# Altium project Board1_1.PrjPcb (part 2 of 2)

## Sheet ETH,HDMI.schdoc
size 420 x 297 mm; Device: Drawing-Symbol_A4; @Board Name: Board1_1; @Page Name: ETH,HDMI; @Create Time: 13:52:28; @Page Count: 7; @Page No: 6; @Schematic Name: Schematic1_1; @Update Time: 13:52:28; @Assembly Variant: Basic; Border: 1; Title Block Position: 3; Size: A4; Region Start: 1; X Region Count: 6; Y Region Count: 4; Blade Width: 10; Width: 1655; Height: 1170; Symbol: Drawing-Symbol_A4; Company: 嘉立创EDA; Version: V1.0; Page Size: A4; @Project Name: N01｜全志 H6 Linux 主板; @Update Date: 2026-11-21; @Create Date: 2026-11-21
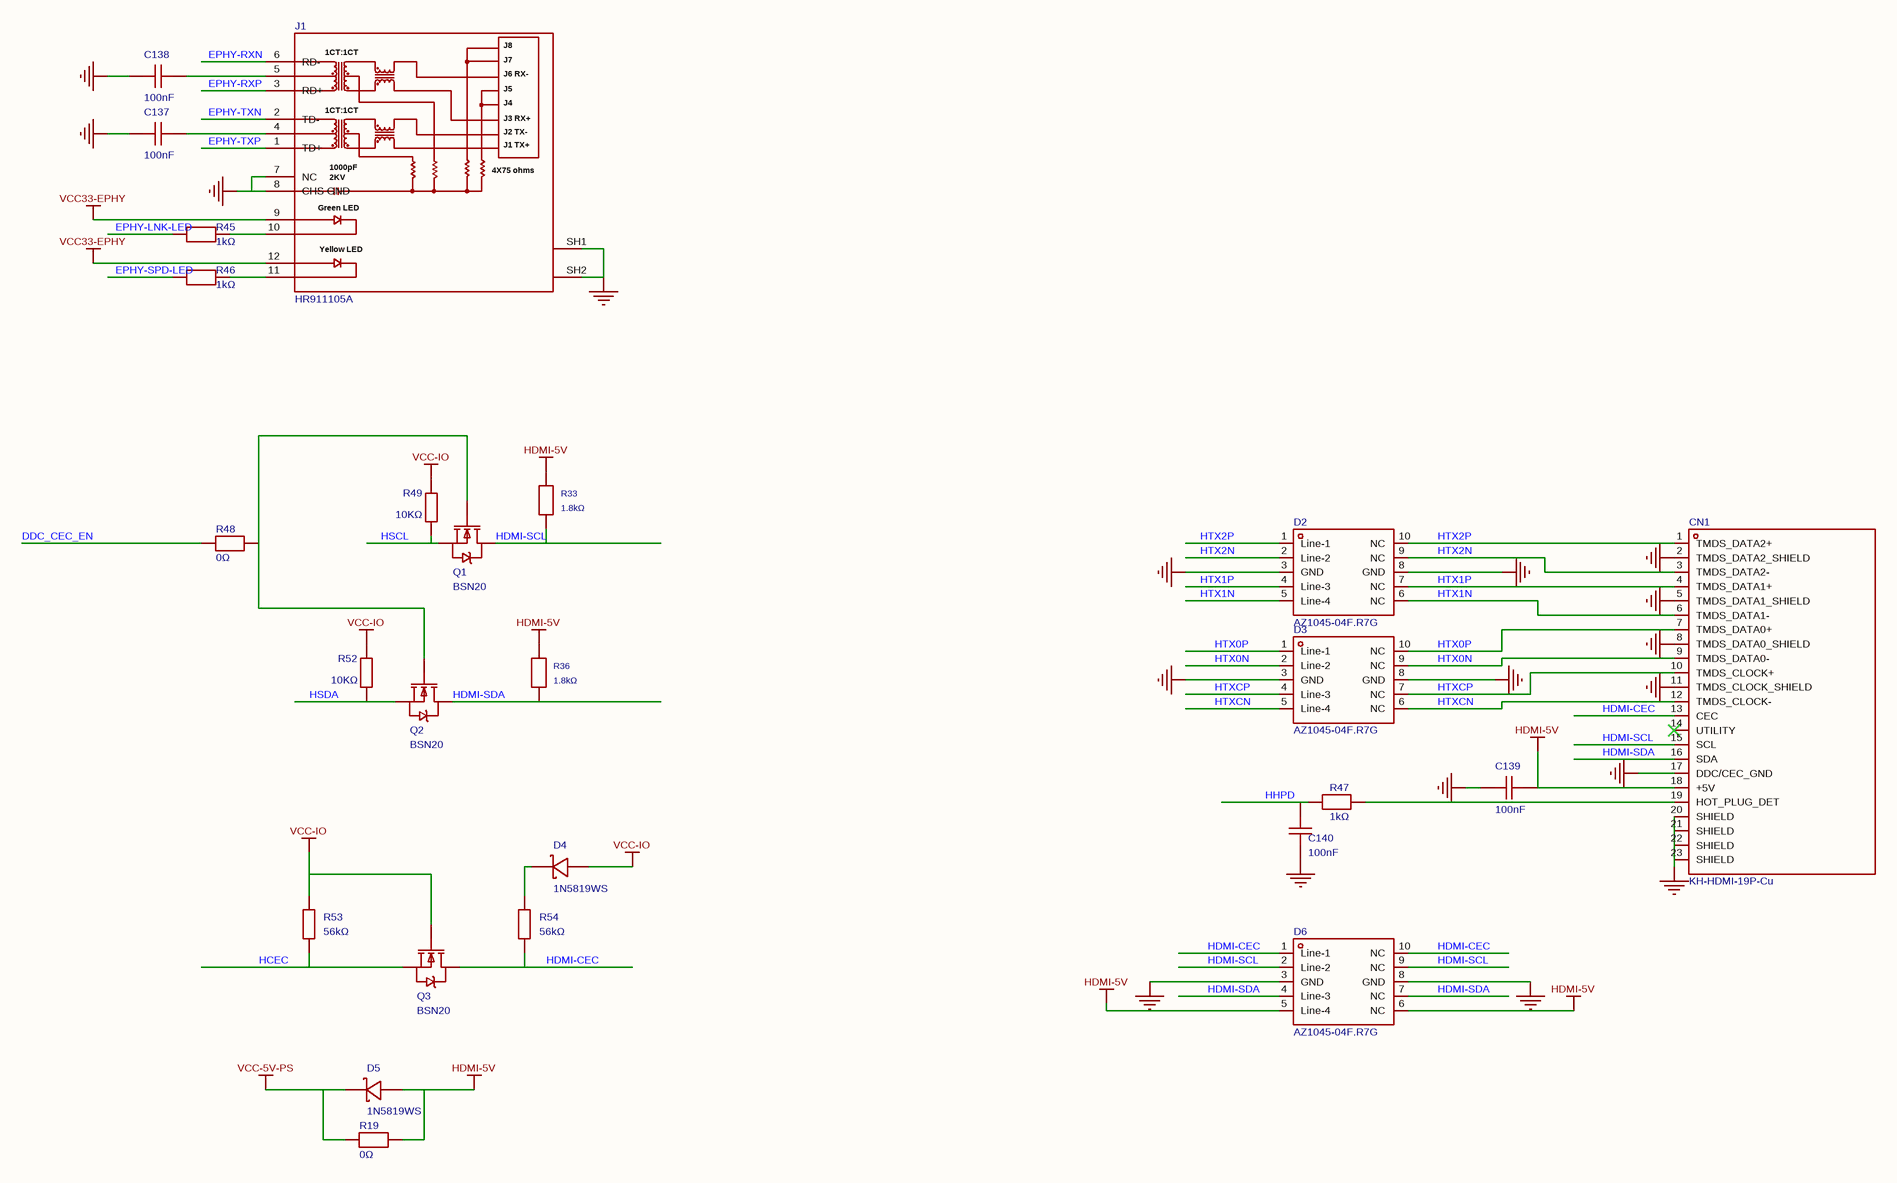
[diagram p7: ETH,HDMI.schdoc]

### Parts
C137  100nF  [C0603]
C138  100nF  [C0603]
C139  100nF  [C0402]
C140  100nF  [C0402]
CN1  KH-HDMI-19P-Cu  [HDMI-SMD_KH-HDMI-19P-CU]
D2  AZ1045-04F.R7G  [DFN2510-10_L2.5-W1.0-P0.50-BL]
D3  AZ1045-04F.R7G  [DFN2510-10_L2.5-W1.0-P0.50-BL]
D4  1N5819WS  [SOD-323_L1.8-W1.3-LS2.5-RD]
D5  1N5819WS  [SOD-323_L1.8-W1.3-LS2.5-RD]
D6  AZ1045-04F.R7G  [DFN2510-10_L2.5-W1.0-P0.50-BL]
J1  HR911105A  [RJ45-TH_HR911105A]
Q1  BSN20  [SOT-23-3_L2.9-W1.6-P1.90-LS2.8-BR]
Q2  BSN20  [SOT-23-3_L2.9-W1.6-P1.90-LS2.8-BR]
Q3  BSN20  [SOT-23-3_L2.9-W1.6-P1.90-LS2.8-BR]
R19  0Ω  [R0805]
R33  1.8kΩ  [R0805]
R36  1.8kΩ  [R0805]
R45  1kΩ  [R0805]
R46  1kΩ  [R0805]
R47  1kΩ  [R0805]
R48  0Ω  [R0805]
R49  10KΩ  [R0805]
R52  10KΩ  [R0805]
R53  56kΩ  [R0805]
R54  56kΩ  [R0805]

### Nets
GND: C137.1 C138.1 C139.2 C140.2 CN1.2(TMDS_DATA2_SHIELD) CN1.5(TMDS_DATA1_SHIELD) CN1.8(TMDS_DATA0_SHIELD) CN1.11(TMDS_CLOCK_SHIELD) CN1.17(DDC/CEC_GND) CN1.20(SHIELD) CN1.21(SHIELD) CN1.22(SHIELD) CN1.23(SHIELD) D2.3(GND) D2.8(GND) D3.3(GND) D3.8(GND) D6.3(GND) D6.8(GND) J1.7(NC) J1.8(CHS_GND) J1.SH1 J1.SH2
HDMI-5V: C139.1 CN1.18(+5V) D5.2(A) D6.5(Line-4) D6.6(NC) R19.2 R33.2 R36.2
VCC33-EPHY: J1.9 J1.12  [project net ALDO2]
VCC-5V-PS: D5.1(K) R19.1  [project net ALDOIN]
VCC-IO: D4.2(A) Q3.1(G) R49.1 R52.1 R53.2  [project net CLDO1]
DDC_CEC_EN: R48.1
EPHY-LNK-LED: R45.1
EPHY-RXN: J1.6(RD-)
EPHY-RXP: J1.3(RD+)
EPHY-SPD-LED: R46.1
EPHY-TXN: J1.2(TD-)
EPHY-TXP: J1.1(TD+)
HCEC: Q3.2(S) R53.1
HDMI-CEC: CN1.13(CEC) D6.1(Line-1) D6.10(NC) Q3.3(D) R54.1
HDMI-SCL: CN1.15(SCL) D6.2(Line-2) D6.9(NC) Q1.3(D) R33.1
HDMI-SDA: CN1.16(SDA) D6.4(Line-3) D6.7(NC) Q2.3(D) R36.1
HHPD: C140.1 R47.1
HSCL: Q1.2(S) R49.2
HSDA: Q2.2(S) R52.2
HTX0N: CN1.9(TMDS_DATA0-) D3.2(Line-2) D3.9(NC)
HTX0P: CN1.7(TMDS_DATA0+) D3.1(Line-1) D3.10(NC)
HTX1N: CN1.6(TMDS_DATA1-) D2.5(Line-4) D2.6(NC)
HTX1P: CN1.4(TMDS_DATA1+) D2.4(Line-3) D2.7(NC)
HTX2N: CN1.3(TMDS_DATA2-) D2.2(Line-2) D2.9(NC)
HTX2P: CN1.1(TMDS_DATA2+) D2.1(Line-1) D2.10(NC)
HTXCN: CN1.12(TMDS_CLOCK-) D3.5(Line-4) D3.6(NC)
HTXCP: CN1.10(TMDS_CLOCK+) D3.4(Line-3) D3.7(NC)
NetC137_2: C137.2 J1.4
NetC138_2: C138.2 J1.5
NetCN1_19: CN1.19(HOT_PLUG_DET) R47.2
NetD4_1: D4.1(K) R54.2
NetJ1_10: J1.10 R45.2
NetJ1_11: J1.11 R46.2
NetQ1_1: Q1.1(G) Q2.1(G) R48.2

Not connected (* = marked no-connect by the designer): CN1 14(UTILITY)*

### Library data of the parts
C137 C138 = CC0603KRX7R9BB104: 容值:100nF;精度:±10%;额定电压:50V;温度系数:X7R;; Manufacturer: YAGEO(国巨); 3D Model: ac125912035d415993ca9572d50418b1¦0819f05c4eef4c71ace90d822a990e87; 3D Model Transform: 62.992,31.496,0,0,0,0,0,0,0; Tolerance: ±10%; Voltage Rating: 50V; Temperature Coefficient: X7R; AddInBom: yes; ModelName: C0603_L1.6-W0.8-H0.8
C139 C140 = CL05B104KO5NNNC: 容值:100nF;精度:±10%;额定电压:16V;温度系数:X7R;; Manufacturer: SAMSUNG(三星); 3D Model: 36a51122f27c49738f86b3bfa98863e0¦0819f05c4eef4c71ace90d822a990e87; 3D Model Transform: 39.37,19.685,0,0,0,0,0,0,0; Tolerance: ±10%; Voltage Rating: 16V; Temperature Coefficient: X7R; AddInBom: yes; ModelName: C0402_L1.0-W0.5-H0.5
CN1 = KH-HDMI-19P-Cu: HDMI高清头母座 19PIN 四脚插端子SMT; Manufacturer: kinghelm(金航标); AddInBom: yes; ModelId: 60339402b69c481f9aa5c918248ca672¦0819f05c4eef4c71ace90d822a990e87; ModelTransform: 590.55,466.5345,0,0,0,0,0.001,-78.739,-66.929; Connector Type: HDMI-A; Gender: 母
D2 = AZ1045-04F.R7G: 反向截止电压(Vrwm):5V;钳位电压:12V;峰值脉冲电流(Ipp):3.5A@8/20us;峰值脉冲功率(Ppp):30W@8/20us;击穿电压:6V;; Manufacturer: AMAZING(晶焱); AddInBom: yes; ModelId: 55525fa8fc914f7c8ffcb10749ea5f73¦0819f05c4eef4c71ace90d822a990e87; ModelName: DFN-10_L2.5-W1.0-H0.5-P0.50; ModelTransform: 40.1574,98.425,0,90,0,0,0,0,0; Reverse Stand-Off Voltage (Vrwm): 5V; Clamping Voltage: 12V; Voltage - Breakdown: 6V; Reverse Leakage Current (Ir): 1.5uA; Number of Channels: 四路; level of protection: IEC 61000-4-5；IEC 61000-4-2; Type: ESD; Junction Capacitance: 0.5pF
D3 D6 = AZ1045-04F.R7G: 反向截止电压(Vrwm):5V;钳位电压:12V;峰值脉冲电流(Ipp):3.5A@8/20us;峰值脉冲功率(Ppp):30W@8/20us;击穿电压:6V;; Manufacturer: AMAZING(晶焱); 3D Model: 55525fa8fc914f7c8ffcb10749ea5f73¦0819f05c4eef4c71ace90d822a990e87; 3D Model Transform: 40.1574,98.425,0,90,0,0,0,0,0; Reverse Stand-Off Voltage (Vrwm): 5V; Clamping Voltage: 12V; Voltage - Breakdown: 6V; Reverse Leakage Current (Ir): 1.5uA; Number of Channels: 四路; level of protection: IEC 61000-4-5；IEC 61000-4-2; Type: ESD; Junction Capacitance: 0.5pF; AddInBom: yes; ModelName: DFN-10_L2.5-W1.0-H0.5-P0.50
D4 D5 = 1N5819WS_C191023: 正向压降(Vf):600mV@1A;直流反向耐压(Vr):40V;整流电流:1A;; Manufacturer: Hottech(合科泰); AddInBom: yes; ModelId: db63db13d9e342eb939127d413d6200b¦0819f05c4eef4c71ace90d822a990e87; ModelTransform: 104.3305,51.181,0,0,0,0,0,-0.004,0; Voltage - DC Reverse(Vr): 40V; Current - Rectified: 1A; Non-Repetitive Peak Forward Surge Current: 25A
J1 = HR911105A_C12074: 连接器类型:RJ45插座;安装方式:弯插;端口数量:1;LED:带LED;屏蔽:有屏蔽;等级:-;触头材质:磷青铜;触头镀层:金;工作温度:0℃~+70℃;; Manufacturer: HANRUN(汉仁); 3D Model: 269ece015cf14129b359f9a66aa2dc0d¦0819f05c4eef4c71ace90d822a990e87; 3D Model Transform: 624.711,850.392,0,0,0,0,0,-89.567,-129.921; Connector Type: RJ45插座; Number of Ports: 1; LED: 带LED; Shielding: 有屏蔽; PoE: 不带PoE; Supplementary Features: 带滤波; AddInBom: yes
Q1-Q3 = BSN20_C116157: 数量:1个N沟道;漏源电压(Vdss):50V;连续漏极电流(Id):100mA;导通电阻(RDS(on)):10Ω@2.75V,0.2A;耗散功率(Pd):-;阈值电压(Vgs(th)):1.5V@250uA;; Manufacturer: SHIKUES(时科); AddInBom: yes; ModelId: 89cb27a44ab2466697082bb9fd73a7d0¦0819f05c4eef4c71ace90d822a990e87; ModelName: SOT-23-3L_L2.9-W1.6-H1.1-LS2.8-P0.95; ModelTransform: 114.173,110.236,0,90,0,0,0,0,0; Number: 1个N沟道; Drain to Source Voltage: 50V; Current - Continuous Drain(Id): 100mA; Input Capacitance(Ciss): 40pF; Reverse Transfer Capacitance (Crss@Vds): 10pF; Type: N沟道; Output Capacitance(Coss): 15pF
R19 R48 = RE0805FAR000: 电阻类型:合金电阻;阻值:0Ω;精度:±1%;功率:500mW;温度系数:±50ppm/℃;安装方式:贴片;; Manufacturer: JIERR(捷而瑞); 3D Model: 37a81e68749a4138bd2dfa6897b24b85¦0819f05c4eef4c71ace90d822a990e87; 3D Model Transform: 78.74,51.181,0,0,0,0,0,-0.0005,0; Tolerance: ±1%; Power(Watts): 500mW; AddInBom: yes; ModelName: R0805_L2.0-W1.3-H0.6
R33 R36 = FRP0805F1801TS: 电阻类型:厚膜电阻;阻值:1.8kΩ;精度:±1%;功率:250mW;工作电压:150V;温度系数:±100ppm/℃;; Manufacturer: FOJAN(富捷); AddInBom: yes; ModelId: 37a81e68749a4138bd2dfa6897b24b85¦0819f05c4eef4c71ace90d822a990e87; ModelName: R0805_L2.0-W1.3-H0.6; ModelTransform: 78.74,51.181,0,0,0,0,0,-0.0005,0; Tolerance: ±1%; Power(Watts): 250mW; Voltage-Supply(Max): 150V
R45-R47 = FRC0805F1001TS: 电阻类型:厚膜电阻;阻值:1kΩ;精度:±1%;功率:125mW;工作电压:150V;温度系数:±100ppm/℃;; Manufacturer: FOJAN(富捷); AddInBom: yes; ModelId: 37a81e68749a4138bd2dfa6897b24b85¦0819f05c4eef4c71ace90d822a990e87; ModelName: R0805_L2.0-W1.3-H0.6; ModelTransform: 78.74,51.181,0,0,0,0,0,-0.0005,0; Tolerance: ±1%; Power(Watts): 125mW; Voltage-Supply(Max): 150V
R49 R52 = 0805W8F1002T5E_C17414: 电阻类型:厚膜电阻;阻值:10kΩ;精度:±1%;功率:125mW;工作电压:150V;温度系数:±100ppm/℃;; Manufacturer: UNI-ROYAL(厚声); Add into BOM: yes; 3D Model: 37a81e68749a4138bd2dfa6897b24b85; 3D Model Transform: 78.74,51.181,0,0,0,0,0,-0.0005,0; Tolerance: ±1%; Power(Watts): 125mW; Voltage-Supply(Max): 150V; ModelName: R0805_L2.0-W1.3-H0.6
R53 R54 = 0805W8F5602T5E: 电阻类型:厚膜电阻;阻值:56kΩ;精度:±1%;功率:125mW;工作电压:150V;温度系数:±100ppm/℃;; Manufacturer: UNI-ROYAL(厚声); AddInBom: yes; ModelId: 37a81e68749a4138bd2dfa6897b24b85¦0819f05c4eef4c71ace90d822a990e87; ModelName: R0805_L2.0-W1.3-H0.6; ModelTransform: 78.74,51.181,0,0,0,0,0,-0.0005,0; Tolerance: ±1%; Power(Watts): 125mW; Voltage-Supply(Max): 150V

## Sheet KEY,DEBUG,LED.schdoc
size 420 x 297 mm; Device: Drawing-Symbol_A4; @Board Name: Board1_1; @Page Name: KEY,DEBUG,LED; @Create Time: 13:52:28; @Page Count: 7; @Page No: 7; @Schematic Name: Schematic1_1; @Update Time: 13:52:28; @Assembly Variant: Basic; Border: 1; Title Block Position: 3; Size: A4; Region Start: 1; X Region Count: 6; Y Region Count: 4; Blade Width: 10; Width: 1655; Height: 1170; Symbol: Drawing-Symbol_A4; Company: 嘉立创EDA; Version: V1.0; Page Size: A4; @Project Name: N01｜全志 H6 Linux 主板; @Update Date: 2026-11-21; @Create Date: 2026-11-21
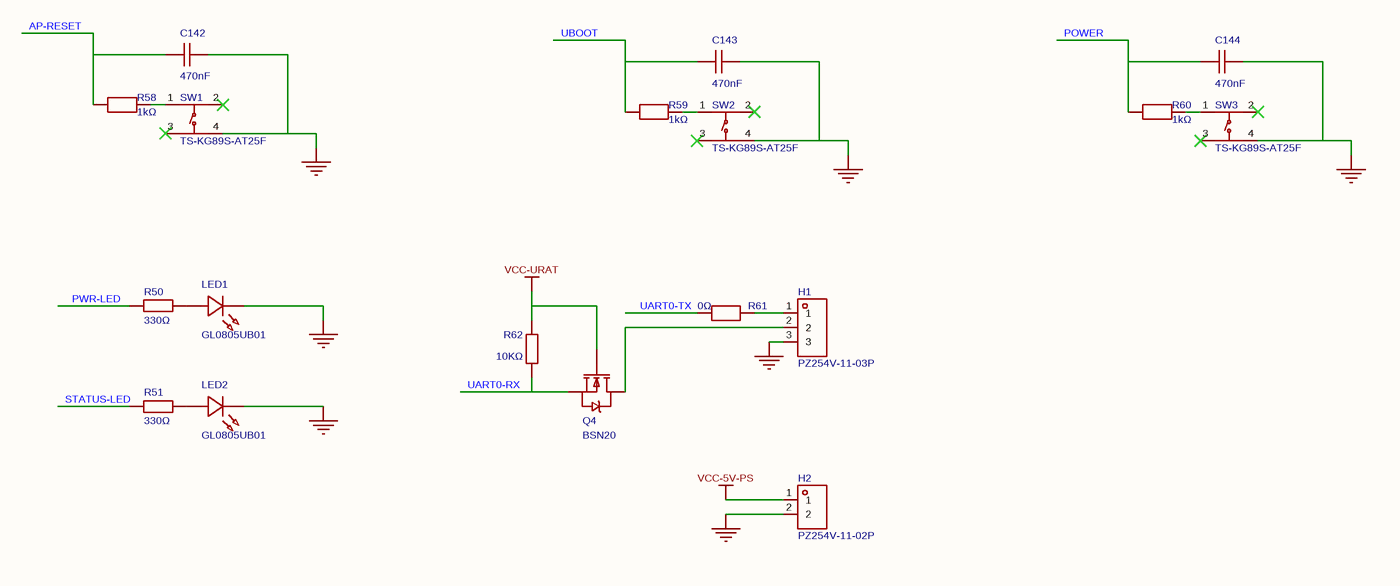
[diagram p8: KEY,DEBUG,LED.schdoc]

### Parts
C142  470nF  [C0603]
C143  470nF  [C0603]
C144  470nF  [C0603]
H1  PZ254V-11-03P  [HDR-TH_3P-P2.54-V-M_PZ254V-11-03P]
H2  PZ254V-11-02P  [HDR-TH_2P-P2.54-V-M]
LED1  GL0805UB01  [LED0805-RD_BLUE]
LED2  GL0805UB01  [LED0805-RD_BLUE]
Q4  BSN20  [SOT-23-3_L2.9-W1.6-P1.90-LS2.8-BR]
R50  330Ω  [R0805]
R51  330Ω  [R0805]
R58  1kΩ  [R0805]
R59  1kΩ  [R0805]
R60  1kΩ  [R0805]
R61  0Ω  [R0805]
R62  10KΩ  [R0805]
SW1  TS-KG89S-AT25F  [SW-SMD_4P-L4.2-W3.3-P2.15-LS5.1]
SW2  TS-KG89S-AT25F  [SW-SMD_4P-L4.2-W3.3-P2.15-LS5.1]
SW3  TS-KG89S-AT25F  [SW-SMD_4P-L4.2-W3.3-P2.15-LS5.1]

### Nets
GND: C142.2 C143.2 C144.2 H1.3 H2.2 LED1.1(K) LED2.1(K) SW1.4 SW2.4 SW3.4
VCC-5V-PS: H2.1  [project net ALDOIN]
VCC-URAT: Q4.1(G) R62.1  [project net CLDO2]
AP-RESET: C142.1 R58.1
POWER: C144.1 R60.1
PWR-LED: R50.1
STATUS-LED: R51.1
UART0-RX: Q4.2(S) R62.2
UART0-TX: R61.1
UBOOT: C143.1 R59.1
NetH1_1: H1.1 R61.2
NetH1_2: H1.2 Q4.3(D)
NetLED1_2: LED1.2(A) R50.2
NetLED2_2: LED2.2(A) R51.2
NetR58_2: R58.2 SW1.1
NetR59_2: R59.2 SW2.1
NetR60_2: R60.2 SW3.1

Not connected (* = marked no-connect by the designer): SW1 2* 3*; SW2 2* 3*; SW3 2* 3*

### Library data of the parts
C142-C144 = CL10B474KA8NNNC: 容值:470nF;精度:±10%;额定电压:25V;温度系数:X7R;; Manufacturer: SAMSUNG(三星); AddInBom: yes; ModelId: ac125912035d415993ca9572d50418b1¦0819f05c4eef4c71ace90d822a990e87; ModelName: C0603_L1.6-W0.8-H0.8; ModelTransform: 62.992,31.496,0,0,0,0,0,0,0; Tolerance: ±10%; Voltage Rating: 25V; Temperature Coefficient: X7R
H1 = PZ254V-11-03P: 插针结构:1x3P;间距:2.54mm;行距:-;圆针/方针:方针;安装方式:直插;排数:单排;总PIN位数:3P;额定电流:3A;额定电压:250V;配合针长度:6mm;塑高:2.5mm;端接针长度:3mm;触头材质:黄铜;触头镀层:镀金;工作温度:-40℃~+105℃;颜色:黑色;; Manufacturer: XFCN(兴飞); Symbol: PZ254V-11-03P_C2937625; AddInBom: yes; ModelId: 44f5efc5b89343eda4a6044a2f4edce0¦0819f05c4eef4c71ace90d822a990e87; ModelTransform: 300.3931,100,0,0,0,0,0,0,-118.11; Pin Structure: 1x3P; Pitch: 2.54mm; Circluar Pins/Square Pins: 方针; Current Rating: 3A; Voltage Rating (Max): 250V
H2 = PZ254V-11-02P: 插针结构:1x2P;间距:2.54mm;行距:-;圆针/方针:方针;安装方式:直插;排数:单排;总PIN位数:2P;额定电流:3A;额定电压:250V;配合针长度:6mm;塑高:2.5mm;端接针长度:3mm;触头材质:黄铜;触头镀层:-;工作温度:-40℃~+105℃;颜色:黑色;; Manufacturer: XFCN(兴飞); AddInBom: yes; ModelId: e35305ec3aa84b66b849f914b715e73f¦0819f05c4eef4c71ace90d822a990e87; ModelName: HDR2.54-M-LI-1X2P; ModelTransform: 200,100,0,0,0,0,0,0,-118.11; Pin Structure: 1x2P; Pitch: 2.54mm; Circluar Pins/Square Pins: 方针; Current Rating: 3A; Voltage Rating (Max): 250V
LED1 LED2 = GL0805UB01: 发光颜色:蓝色;正向压降(Vf):3.1V;正向电流:20mA；5mA;波长:457nm~475nm;二极管配置:独立二极管;透镜颜色:无色透明透镜;发光强度:80mcd;发光角度:120°;载带方式:正贴;工作温度:-40℃~+85℃;; Manufacturer: Guiguang light(桂光光电); 3D Model: 6ccd75a2b5134d6ab756ecf3c14a7290¦0819f05c4eef4c71ace90d822a990e87; 3D Model Transform: 79.527,49.2125,0,0,0,0,0,0,0; Illumination Color: 蓝色; Voltage - Forward(Vf): 3.1V; Diode Configuration: 独立二极管; Lens Color: 无色透明透镜; Luminous Intensity: 80mcd; Viewing Angle: 120°; AddInBom: yes; ModelName: LED0805-RD
Q4 = BSN20_C116157: 数量:1个N沟道;漏源电压(Vdss):50V;连续漏极电流(Id):100mA;导通电阻(RDS(on)):10Ω@2.75V,0.2A;耗散功率(Pd):-;阈值电压(Vgs(th)):1.5V@250uA;; Manufacturer: SHIKUES(时科); 3D Model: 89cb27a44ab2466697082bb9fd73a7d0¦0819f05c4eef4c71ace90d822a990e87; 3D Model Transform: 114.173,110.236,0,90,0,0,0,0,0; Number: 1个N沟道; Drain to Source Voltage: 50V; Current - Continuous Drain(Id): 100mA; Input Capacitance(Ciss): 40pF; Reverse Transfer Capacitance (Crss@Vds): 10pF; Type: N沟道; Output Capacitance(Coss): 15pF; AddInBom: yes; ModelName: SOT-23-3L_L2.9-W1.6-H1.1-LS2.8-P0.95
R50 R51 = 0805W8F3300T5E: 电阻类型:厚膜电阻;阻值:330Ω;精度:±1%;功率:125mW;工作电压:150V;温度系数:±100ppm/℃;; Manufacturer: UNI-ROYAL(厚声); AddInBom: yes; ModelId: 37a81e68749a4138bd2dfa6897b24b85¦0819f05c4eef4c71ace90d822a990e87; ModelName: R0805_L2.0-W1.3-H0.6; ModelTransform: 78.74,51.181,0,0,0,0,0,-0.0005,0; Tolerance: ±1%; Power(Watts): 125mW; Voltage-Supply(Max): 150V
R58-R60 = FRC0805F1001TS: 电阻类型:厚膜电阻;阻值:1kΩ;精度:±1%;功率:125mW;工作电压:150V;温度系数:±100ppm/℃;; Manufacturer: FOJAN(富捷); 3D Model: 37a81e68749a4138bd2dfa6897b24b85¦0819f05c4eef4c71ace90d822a990e87; 3D Model Transform: 78.74,51.181,0,0,0,0,0,-0.0005,0; Tolerance: ±1%; Power(Watts): 125mW; Voltage-Supply(Max): 150V; AddInBom: yes; ModelName: R0805_L2.0-W1.3-H0.6
R61 = RE0805FAR000: as R19 on sheet ETH,HDMI
R62 = 0805W8F1002T5E_C17414: as R49 on sheet ETH,HDMI
SW1-SW3 = TS-KG89S-AT25F: 电路结构:单刀单掷;按钮形状:椭圆形按钮;作用力:250gf;安装方式:立贴;开关长度:4.2mm;开关宽度:3.25mm;开关高度:2.5mm;带支架:不带;触点电流:50mA;额定电压(DC):12V;绝缘电阻:100MΩ;机械寿命:10万次;; Manufacturer: HANBO(汉博); 3D Model: 101da67941e24d4e9615179a94fc6132¦0819f05c4eef4c71ace90d822a990e87; 3D Model Transform: 204.724,127.9525,0,0,0,0,0,0,0; Circuit: 单刀单掷; Actuator Style: 椭圆形按钮; Operating Force: 250gf; Switch Length: 4.2mm; Switch Width: 3.25mm; Switch Height: 2.5mm; Strike Gundam: 不带; Contact Current: 50mA; Voltage Rating (DC): 12V; Insulation Resistance: 100MΩ; Actuator/Cap Color: 白色; Pin Style: SMD接片; Mechanical Life: 10万次; AddInBom: yes; ModelName: SW-SMD_4P-L4.2-W3.3-H2.5-P2.15-LS5.1

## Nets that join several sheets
ALDO1: H6_SOC_2 (U2.H6 U2.H18 U2.M19), H6_SOC_1 (6 pins), Power_Tree_1 (C18.2 R2.1 R3.1 U1.28)
ALDO2: H6_SOC_1 (11 pins), Power_Tree_1 (C17.2 U1.31), ETH,HDMI (J1.9 J1.12)
ALDOIN: SD,USB,CODEC (10 pins), Power_Tree_1 (19 pins), ETH,HDMI (D5.1 R19.1), KEY,DEBUG,LED (H2.1)
BLDO1: Lpddr3 (C108.2 U2.W22), H6_SOC_1 (6 pins), Power_Tree_1 (C2.2 U1.2)
BLDO2: H6_SOC_2 (U2.N19), H6_SOC_1 (7 pins), Power_Tree_1 (C1.2 U1.1)
CLDO1: SD,USB,CODEC (10 pins), H6_SOC_2 (R8.1), H6_SOC_1 (5 pins), Power_Tree_1 (C13.2 U1.19), ETH,HDMI (5 pins)
CLDO2: H6_SOC_2 (U2.R6), H6_SOC_1 (C36.2), Power_Tree_1 (C14.2 U1.20), KEY,DEBUG,LED (Q4.1 R62.1)
DCDCD: H6_SOC_1 (19 pins), Power_Tree_1 (C6.2 L8.1 U1.9)
DCDCE: Lpddr3 (74 pins), Power_Tree_1 (C8.2 L7.1 U1.10)
GND: SD,USB,CODEC (53 pins), Lpddr3 (95 pins), H6_SOC_1 (216 pins), Power_Tree_1 (35 pins), ETH,HDMI (23 pins), KEY,DEBUG,LED (10 pins)
VCC18-LPDDR3: Lpddr3 (13 pins), Power_Tree_1 (R6.2)
VCC18-RTC: H6_SOC_1 (R11.1 U2.F20), Power_Tree_1 (5 pins)
VDD-CPU: H6_SOC_1 (15 pins), Power_Tree_1 (C10.2 C15.2 L9.1 L10.1)
VDD-GPU: H6_SOC_1 (13 pins), Power_Tree_1 (C21.2 L1.1)
AP-NMI: H6_SOC_1 (C83.2 U2.G21), Power_Tree_1 (R56.2 U1.16)
AP-RESET: H6_SOC_1 (C84.2 R11.2 U2.G22), Power_Tree_1 (C11.2 U1.15), KEY,DEBUG,LED (C142.1 R58.1)
DDC_CEC_EN: H6_SOC_2 (U2.E11), ETH,HDMI (R48.1)
EPHY-LNK-LED: H6_SOC_1 (U2.B7), ETH,HDMI (R45.1)
EPHY-RXN: H6_SOC_1 (U2.B6), ETH,HDMI (J1.6)
EPHY-RXP: H6_SOC_1 (U2.A6), ETH,HDMI (J1.3)
EPHY-SPD-LED: H6_SOC_1 (U2.C5), ETH,HDMI (R46.1)
EPHY-TXN: H6_SOC_1 (U2.B5), ETH,HDMI (J1.2)
EPHY-TXP: H6_SOC_1 (U2.A5), ETH,HDMI (J1.1)
HCEC: H6_SOC_2 (U2.E9), ETH,HDMI (Q3.2 R53.1)
HHPD: H6_SOC_1 (U2.C20), ETH,HDMI (C140.1 R47.1)
HSCL: H6_SOC_2 (U2.E10), ETH,HDMI (Q1.2 R49.2)
HSDA: H6_SOC_2 (U2.F7), ETH,HDMI (Q2.2 R52.2)
HTX0N: H6_SOC_1 (U2.B19), ETH,HDMI (CN1.9 D3.2 D3.9)
HTX0P: H6_SOC_1 (U2.A19), ETH,HDMI (CN1.7 D3.1 D3.10)
HTX1N: H6_SOC_1 (U2.B18), ETH,HDMI (CN1.6 D2.5 D2.6)
HTX1P: H6_SOC_1 (U2.A18), ETH,HDMI (CN1.4 D2.4 D2.7)
HTX2N: H6_SOC_1 (U2.B17), ETH,HDMI (CN1.3 D2.2 D2.9)
HTX2P: H6_SOC_1 (U2.A17), ETH,HDMI (CN1.1 D2.1 D2.10)
HTXCN: H6_SOC_1 (U2.B20), ETH,HDMI (CN1.12 D3.5 D3.6)
HTXCP: H6_SOC_1 (U2.A20), ETH,HDMI (CN1.10 D3.4 D3.7)
LINEOUTL: SD,USB,CODEC (C145.2), H6_SOC_1 (U2.D2)
LINEOUTR: SD,USB,CODEC (C146.2), H6_SOC_1 (U2.D1)
PMU-SCK: H6_SOC_2 (U2.K20), Power_Tree_1 (R2.2 U1.23)
PMU-SDA: H6_SOC_2 (U2.K23), Power_Tree_1 (R3.2 U1.24)
POWER: Power_Tree_1 (U1.27), KEY,DEBUG,LED (C144.1 R60.1)
PWR-LED: H6_SOC_2 (U2.K21), KEY,DEBUG,LED (R50.1)
SDC0-CLK: SD,USB,CODEC (U3.5), H6_SOC_2 (R23.2)
SDC0-CMD: SD,USB,CODEC (R27.1 U3.3), H6_SOC_2 (U2.G3)
SDC0-D0: SD,USB,CODEC (R28.1 U3.7), H6_SOC_2 (U2.F3)
SDC0-D1: SD,USB,CODEC (R29.1 U3.8), H6_SOC_2 (U2.E2)
SDC0-D2: SD,USB,CODEC (R25.1 U3.1), H6_SOC_2 (U2.G2)
SDC0-D3: SD,USB,CODEC (R26.1 U3.2), H6_SOC_2 (U2.F1)
SDC0-DET: SD,USB,CODEC (R57.1 U3.CD), H6_SOC_2 (U2.C8)
STATUS-LED: H6_SOC_2 (U2.J21), KEY,DEBUG,LED (R51.1)
UART0-RX: H6_SOC_2 (U2.D12), KEY,DEBUG,LED (Q4.2 R62.2)
UART0-TX: H6_SOC_2 (U2.C9), KEY,DEBUG,LED (R61.1)
UBOOT: H6_SOC_1 (U2.G17), KEY,DEBUG,LED (C143.1 R59.1)
USB0-DM: SD,USB,CODEC (USB2.2), H6_SOC_1 (U2.A13)
USB0-DP: SD,USB,CODEC (USB2.3), H6_SOC_1 (U2.B13)
USB0-DRVVBUS: SD,USB,CODEC (R31.2 R34.2 U4.4 U7.4), H6_SOC_2 (U2.H20)
USB1-DM: SD,USB,CODEC (USB3.11), H6_SOC_1 (U2.B16)
USB1-DP: SD,USB,CODEC (USB3.12), H6_SOC_1 (U2.C16)
USB1-SSRXN: SD,USB,CODEC (D1.1 D1.10 USB3.14), H6_SOC_1 (U2.A14)
USB1-SSRXP: SD,USB,CODEC (D1.2 D1.9 USB3.15), H6_SOC_1 (U2.B14)
USB1-SSTXN: SD,USB,CODEC (D1.4 D1.7 USB3.17), H6_SOC_1 (C23.2)
USB1-SSTXP: SD,USB,CODEC (D1.5 D1.6 USB3.18), H6_SOC_1 (C22.2)
USB3-DM: SD,USB,CODEC (USB3.2), H6_SOC_1 (U2.A12)
USB3-DP: SD,USB,CODEC (USB3.3), H6_SOC_1 (U2.B12)
VDD-CPUFB: H6_SOC_1 (U2.R16 U2.T17), Power_Tree_1 (U1.39 U1.40)
VDD-GPUFB: H6_SOC_1 (U2.R7), Power_Tree_1 (U1.47)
